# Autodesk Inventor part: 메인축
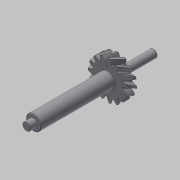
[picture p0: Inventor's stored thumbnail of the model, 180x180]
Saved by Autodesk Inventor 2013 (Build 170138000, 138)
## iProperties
Created: 2016-12
Part Number: 메인축
Material: 강철, 탄소
Document SubType Name: Modeling
Designer: mduedu
Categories: <?xml version="1.0" encoding="UTF-16"?> <MemberInstance><Categories><FamilyTemplate><FamilyTemplateParameter ValueType="xs:double" Id="1" ObjectReferenceKey="da
Density: 7.87 g/cm^3
Mass: 199.41 g
Surface Area: 86.9446 cm^2
Volume: 25.338 cm^3
CustomPartVersion: 1
Author: mduedu
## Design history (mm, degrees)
sketch "Sketch1"
  geometry: C1 r 19.321 at (0, 0)
  constraints: 1 centre point
  dimensions: "d0" = 38.64102 diameter of C1 (= da_da)
extrude "Extrusion1" new body sketch "Sketch1" distance "d1" = 10 (= da_b); taper "d2" = 0 deg
workplane "Work Plane2"
sketch "Sketch2"
  geometry: C1 r 19.321 at (0, 0) reference; C2 r 17.321 at (0, 0)
  constraints: 1 centre point, 1 coincident
  dimensions: "d3" = 34.64102 diameter of C2 (= da_dw)
feature "피치 지름" sketch "Sketch2" dims "d4" = 10, "d5" = 0
workplane "Work Plane8"
workplane "Work Plane9"
feature "스퍼 기어" dims "da_b" = 10, "da_d" = 34.64102, "da_aw" = 43.87862, "da_da" = 38.64102, "da_df" = 29.64102, "da_dw" = 34.64102, angle "da_beta" = 30 deg, "da_lefttooth" = 0, "da_righttooth" = 10
sketch "스케치3"
  geometry: C1 r 7.5 at (0, 0); 1 further point
  constraints: 1 centre point, 1 coincident
  dimensions: "d49" = 15 diameter of C1
extrude "돌출2" join sketch "스케치3" distance "d50" = 74; taper "d51" = 0 deg
sketch "스케치4"
  geometry: C1 r 4 at (0, 0); 1 further point
  constraints: 1 centre point, 1 coincident
  dimensions: "d52" = 8 diameter of C1
extrude "돌출3" join sketch "스케치4" distance "d53" = 7; taper "d54" = 0 deg
sketch "스케치5"
  geometry: C1 r 7.5 at (0, 0) reference; 1 further point
extrude "돌출4" join sketch "스케치5" distance "d55" = 6; taper "d56" = 0 deg
sketch "스케치6"
  geometry: C1 r 4 at (0, 0); 1 further point
  constraints: 1 centre point, 1 coincident
  dimensions: "d57" = 8 diameter of C1
extrude "돌출5" join sketch "스케치6" distance "d58" = 30; taper "d59" = 0 deg
chamfer "모따기1" distance "d60" = 0.5; stored, may be unused: second distance "d61" = 2, angle "d62" = 45 deg
fillet "모깎기1" dims "d63" = 0.5
sketch "스케치7" dims "d64" = 25
  geometry: C1 r 1 at (0, 12.5); 2 further points
  constraints: 2 vertical alignment, 1 centre point, 1 coincident, 2 other
  dimensions: "d65" = 2 diameter of C1
extrude "돌출6" join sketch "스케치7" distance "d66" = 0.5; taper "d67" = 0 deg
body "Solid1"
body "Srf1"
other parameters: "d16" = 43.87862 (= da_aw), "d17" = 0, "d34" = 12 deg (computed from da_z), "d39" = 0, "d41" = 0, "d43" = 43.87862 (= da_aw), "d46" = 43.87862 (= da_aw), "d47" = 0, "d48" = 0
